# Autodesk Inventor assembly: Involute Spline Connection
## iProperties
Created: 2007-11
Part Number: Involute Spline Connection
Document SubType Name: Assembly
Designer: CM
ClientObjectVersion: 1
Author: CM
